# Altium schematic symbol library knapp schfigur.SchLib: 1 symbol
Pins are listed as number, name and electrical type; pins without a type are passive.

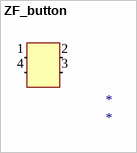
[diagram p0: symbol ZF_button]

## ZF_button
designator *
footprint ZF-button
pins: 1 (out), 2 (out), 3 (out), 4 (out)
